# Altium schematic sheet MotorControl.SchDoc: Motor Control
size A4; SheetNumber: 17; SheetTotal: 23
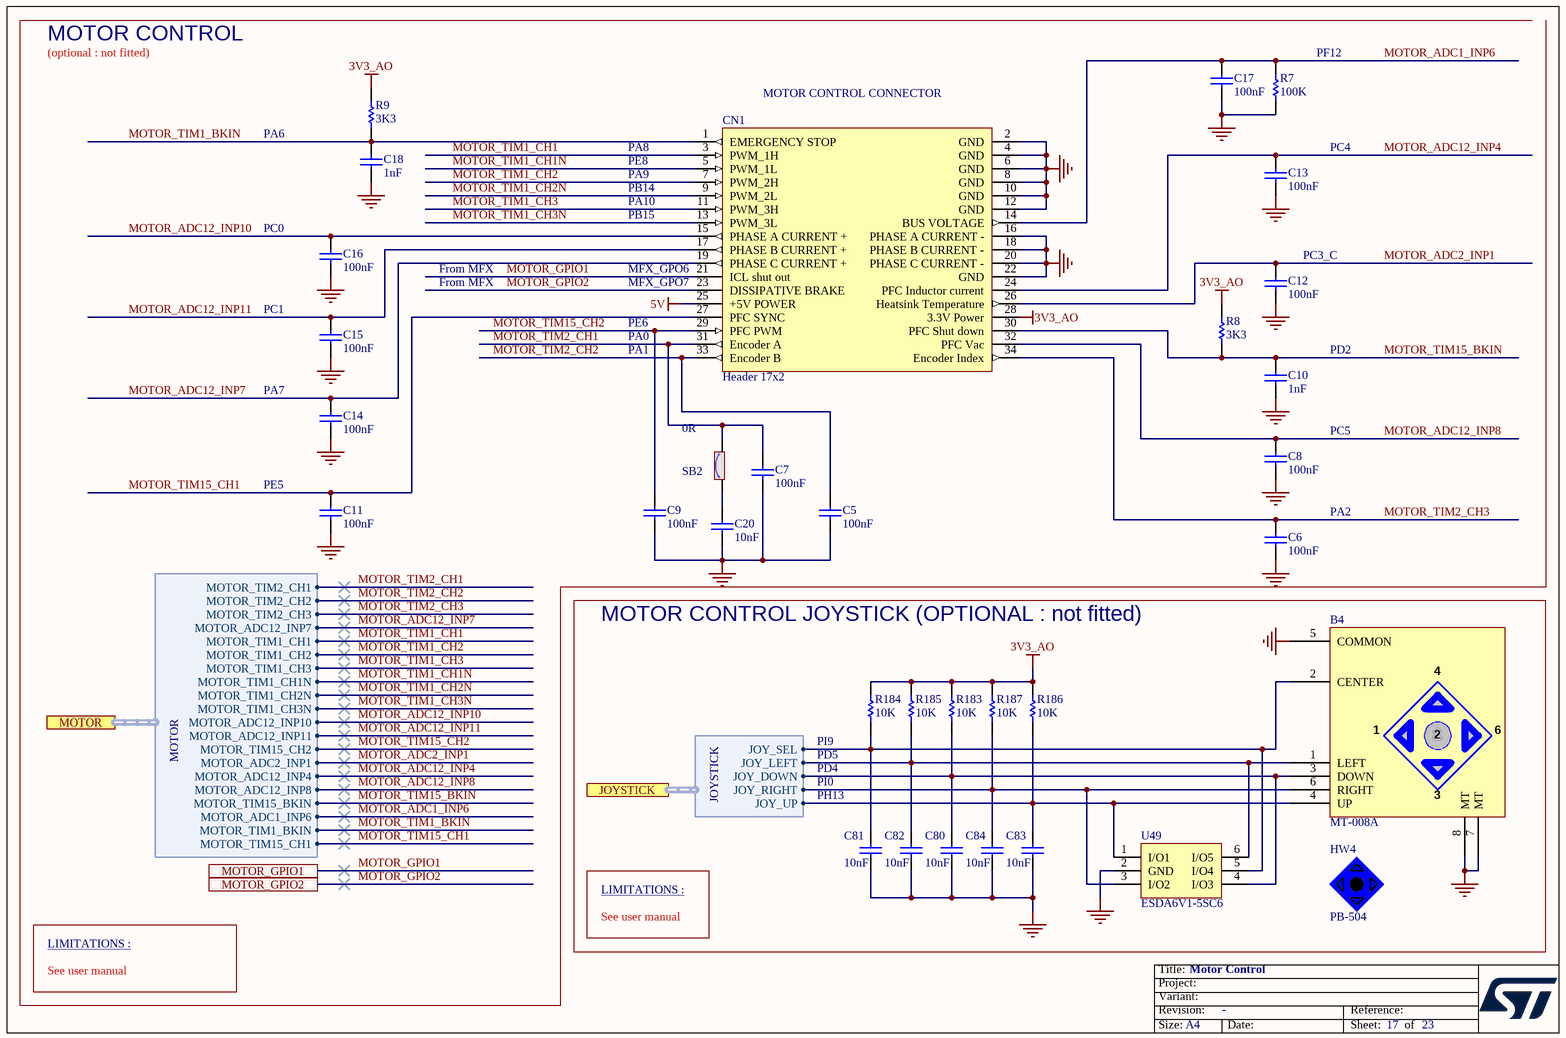
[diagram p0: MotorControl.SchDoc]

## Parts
B4  value MT-008A  [SWI_XIEJIA_MT-008A_6P]  (hidden comment: Joystick MT-008A_M)
C5  value 100nF  [C0402]  (hidden comment: Capacitor)
C6  value 100nF  [C0402]  (hidden comment: Capacitor)
C7  value 100nF  [C0402]  (hidden comment: Capacitor)
C8  value 100nF  [C0402]  (hidden comment: Capacitor)
C9  value 100nF  [C0402]  (hidden comment: Capacitor)
C10  value 1nF  [C0402]  (hidden comment: Capacitor)
C11  value 100nF  [C0402]  (hidden comment: Capacitor)
C12  value 100nF  [C0402]  (hidden comment: Capacitor)
C13  value 100nF  [C0402]  (hidden comment: Capacitor)
C14  value 100nF  [C0402]  (hidden comment: Capacitor)
C15  value 100nF  [C0402]  (hidden comment: Capacitor)
C16  value 100nF  [C0402]  (hidden comment: Capacitor)
C17  value 100nF  [C0402]  (hidden comment: Capacitor)
C18  value 1nF  [C0402]  (hidden comment: Capacitor)
C20  value 10nF  [C0402]  (hidden comment: Capacitor)
C80  value 10nF  [C0402]  (hidden comment: Capacitor)
C81  value 10nF  [C0402]  (hidden comment: Capacitor)
C82  value 10nF  [C0402]  (hidden comment: Capacitor)
C83  value 10nF  [C0402]  (hidden comment: Capacitor)
C84  value 10nF  [C0402]  (hidden comment: Capacitor)
CN1  value Header 17x2  [CON_SAMTEC_TST-117-01-T-D]  (hidden comment: Header 17x2 IDC34 MotorControl)
HW4  value PB-504  (hidden comment: JOYSTICK_BLUE_HAT)  (mechanical)
R7  value 100K  [R0603]  (hidden comment: Resistor)
R8  value 3K3  [R0402]  (hidden comment: Resistor)
R9  value 3K3  [R0402]  (hidden comment: Resistor)
R183  value 10K  [R0402]  (hidden comment: Resistor)
R184  value 10K  [R0402]  (hidden comment: Resistor)
R185  value 10K  [R0402]  (hidden comment: Resistor)
R186  value 10K  [R0402]  (hidden comment: Resistor)
R187  value 10K  [R0402]  (hidden comment: Resistor)
SB2  value 0R  [SOLDER-BRIDGE_R0603-0R]  (hidden comment: SB_ON)
U49  ESDA6V1-5SC6  [ESD_SOT23-6L]

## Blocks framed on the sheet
MOTOR CONTROL JOYSTICK (OPTIONAL : not fitted): B4 C80-C84 HW4 R183-R187 U49

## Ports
JOYSTICK (harness JOYSTICK), MOTOR (harness MOTOR), MOTOR_GPIO1, MOTOR_GPIO2

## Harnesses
MOTOR: MOTOR_TIM2_CH1, MOTOR_TIM2_CH2, MOTOR_TIM2_CH3, MOTOR_ADC12_INP7, MOTOR_TIM1_CH1, MOTOR_TIM1_CH2, MOTOR_TIM1_CH3, MOTOR_TIM1_CH1N, MOTOR_TIM1_CH2N, MOTOR_TIM1_CH3N, MOTOR_ADC12_INP10, MOTOR_ADC12_INP11, MOTOR_TIM15_CH2, MOTOR_ADC2_INP1, MOTOR_ADC12_INP4, MOTOR_ADC12_INP8, MOTOR_TIM15_BKIN, MOTOR_ADC1_INP6, MOTOR_TIM1_BKIN, MOTOR_TIM15_CH1
JOYSTICK: JOY_SEL, JOY_LEFT, JOY_DOWN, JOY_RIGHT, JOY_UP

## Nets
3V3_AO: CN1.28(3.3V_Power) R8.2 R9.2 R183.2 R184.2 R185.2 R186.2 R187.2
5V: CN1.25(+5V_POWER)
GND: B4.5(COMMON) B4.7(MT) B4.8(MT) C5.1 C6.1 C7.1 C8.1 C9.1 C10.1 C11.1 C12.1 C13.1 C14.1 C15.1 C16.1 C17.1 C18.1 C20.1 C80.1 C81.1 C82.1 C83.1 C84.1 CN1.2(GND) CN1.4(GND) CN1.6(GND) CN1.8(GND) CN1.10(GND) CN1.12(GND) CN1.16(PHASE_A_CURRENT_-) CN1.18(PHASE_B_CURRENT_-) CN1.20(PHASE_C_CURRENT_-) CN1.22(GND) R7.1 U49.2(GND)
MOTOR_ADC1_INP6: C17.2 CN1.14(BUS_VOLTAGE) R7.2 ; port MOTOR.MOTOR_ADC1_INP6
MOTOR_ADC2_INP1: C12.2 CN1.26(Heatsink_Temperature) ; port MOTOR.MOTOR_ADC2_INP1
MOTOR_ADC12_INP4: C13.2 CN1.24(PFC_Inductor_current) ; port MOTOR.MOTOR_ADC12_INP4
MOTOR_ADC12_INP7: C14.2 CN1.19(PHASE_C_CURRENT_+) ; port MOTOR.MOTOR_ADC12_INP7
MOTOR_ADC12_INP8: C8.2 CN1.32(PFC_Vac) ; port MOTOR.MOTOR_ADC12_INP8
MOTOR_ADC12_INP10: C16.2 CN1.15(PHASE_A_CURRENT_+) ; port MOTOR.MOTOR_ADC12_INP10
MOTOR_ADC12_INP11: C15.2 CN1.17(PHASE_B_CURRENT_+) ; port MOTOR.MOTOR_ADC12_INP11
MOTOR_GPIO1: CN1.21(ICL_shut_out) ; port MOTOR_GPIO1
MOTOR_GPIO2: CN1.23(DISSIPATIVE_BRAKE) ; port MOTOR_GPIO2
MOTOR_TIM1_BKIN: C18.2 CN1.1(EMERGENCY_STOP) R9.1 ; port MOTOR.MOTOR_TIM1_BKIN
MOTOR_TIM1_CH1: CN1.3(PWM_1H) ; port MOTOR.MOTOR_TIM1_CH1
MOTOR_TIM1_CH1N: CN1.5(PWM_1L) ; port MOTOR.MOTOR_TIM1_CH1N
MOTOR_TIM1_CH2: CN1.7(PWM_2H) ; port MOTOR.MOTOR_TIM1_CH2
MOTOR_TIM1_CH2N: CN1.9(PWM_2L) ; port MOTOR.MOTOR_TIM1_CH2N
MOTOR_TIM1_CH3: CN1.11(PWM_3H) ; port MOTOR.MOTOR_TIM1_CH3
MOTOR_TIM1_CH3N: CN1.13(PWM_3L) ; port MOTOR.MOTOR_TIM1_CH3N
MOTOR_TIM2_CH1: C7.2 CN1.31(Encoder_A) SB2.1 ; port MOTOR.MOTOR_TIM2_CH1
MOTOR_TIM2_CH2: C5.2 CN1.33(Encoder_B) ; port MOTOR.MOTOR_TIM2_CH2
MOTOR_TIM2_CH3: C6.2 CN1.34(Encoder_Index) ; port MOTOR.MOTOR_TIM2_CH3
MOTOR_TIM15_BKIN: C10.2 CN1.30(PFC_Shut_down) R8.1 ; port MOTOR.MOTOR_TIM15_BKIN
MOTOR_TIM15_CH1: C11.2 CN1.27(PFC_SYNC) ; port MOTOR.MOTOR_TIM15_CH1
MOTOR_TIM15_CH2: C9.2 CN1.29(PFC_PWM) ; port MOTOR.MOTOR_TIM15_CH2
NetB4_1: B4.1(LEFT) C82.2 R185.1 U49.6(I/O5) ; port JOYSTICK.JOY_LEFT
NetB4_2: B4.2(CENTER) C81.2 R184.1 U49.5(I/O4) ; port JOYSTICK.JOY_SEL
NetB4_3: B4.3(DOWN) C80.2 R183.1 U49.4(I/O3) ; port JOYSTICK.JOY_DOWN
NetB4_4: B4.4(UP) C83.2 R186.1 U49.1(I/O1) ; port JOYSTICK.JOY_UP
NetB4_6: B4.6(RIGHT) C84.2 R187.1 U49.3(I/O2) ; port JOYSTICK.JOY_RIGHT
NetC20_2: C20.2 SB2.2

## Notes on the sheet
- MOTOR CONTROL
- (optional : not fitted)
- (near CN1) MOTOR CONTROL CONNECTOR
- (near R7) PF12
- PA6
- PA9
- PA8
- PE8
- PC4
- (near C16) PC0
- PB14
- PB15
- PA10
- PC1
- From MFX
- (near CN1) MFX_GPO6
- (near CN1) MFX_GPO7
- (near C12) PC3_C
- PA1
- PA0
- PE6
- PD2
- PA7
- PC5
- PE5
- PA2
- (near R184) PD5
- PD4
- PI0
- (near R184) PI9
- PH13
- LIMITATIONS :
- See user manual

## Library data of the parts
B4 = MCD-00132: Joystick, 4 dir, 1 OK; Part_Type: Misc; Manufacturer: XIEJIA Electronics; BMS_Part_Number: 9180124; Part_Preference: Recommended; Provided_By: SUBCO; Component_Country_Of_Origin: Unknown; ID: 2736; ShowFields: YES
C5-C9 C11-C17 = MCD-00006: Capacitor, MLCC, 100nF, 16V, X7R, 10%, 0402, T=0.5mm; Manufacturer_Part_Number: CC0402KRX7R7BB104; Manufacturer: YAGEO; Alternate_Manufacturer_Part_Number: GCM155R71C104KA55D; Alternate_Manufacturer: MURATA; Part_Preference: Recommended; Partial_Alternate_Internal_Part_Number: MCD-03299; Provided_By: SUBCO; ECCN_US: EAR99; ECCN_EU: NEC; Component_Country_Of_Origin: China; ID: 2474; Order_Code_RS: 9402047; ShowFields: YES
C10 C18 = MCD-00198: Capacitor, MLCC, 1nF, 16V, X7R, 10%, 0402, T=0.5mm; Manufacturer_Part_Number: CC0402KRX7R7BB102; Manufacturer: YAGEO; Part_Preference: Recommended; Provided_By: SUBCO; ECCN_US: EAR99; ECCN_EU: NEC; Component_Country_Of_Origin: China; ID: 2665; ShowFields: YES
C20 C80-C84 = MCD-00011: Capacitor, MLCC, 10nF, 16V, X7R, 10%, 0402, T=0.5mm; Manufacturer_Part_Number: CC0402KRX7R7BB103; Manufacturer: YAGEO; Part_Preference: Recommended; Provided_By: SUBCO; ECCN_US: EAR99; ECCN_EU: NEC; Component_Country_Of_Origin: China; ID: 2469; Order_Code_RS: 3019275; ShowFields: YES
CN1 = MCD-00583: Header, 17x2, 2.54mm, VR, TH, Height 8.89mm/2.92mm, shrouded; Manufacturer_Part_Number: TST-117-01-T-D; Manufacturer: SAMTEC; Part_Type: Connector; Alternate_Manufacturer_Part_Number: BHFS03-34G01BT1; Alternate_Manufacturer: WINPIN; Part_Preference: Recommended; Provided_By: SUBCO; Component_Country_Of_Origin: China, Costa Rica, Malaysia, USA, Vietnam; ID: 3161; ShowFields: YES
HW4 = MCD-01337: Joystick Blue Hat; Part_Type: Misc; Manufacturer: JIUBABA; Part_Preference: Alternate; Provided_By: SUBCO; Alternate_EMS: A; Component_Country_Of_Origin: Unknown; ID: 3437; ShowFields: YES
R7 = MCD-00223: Resistor,100K,0603,1%,1/10W; Manufacturer_Part_Number: RC0603FR-07100KL; Manufacturer: YAGEO; Part_Preference: Recommended; Provided_By: SUBCO; ECCN_US: EAR99; ECCN_EU: NEC; Component_Country_Of_Origin: China; ID: 2647; ShowFields: YES
R8 R9 = MCD-00184: Resistor,3K3,0402,1%,1/16W; Manufacturer_Part_Number: RC0402FR-073K3L; Manufacturer: YAGEO; BMS_Part_Number: 9131946; Part_Preference: Recommended; Provided_By: SUBCO; ECCN_US: EAR99; ECCN_EU: NEC; Component_Country_Of_Origin: China; ID: 2684; ShowFields: YES
R183-R187 = MCD-00053: Resistor,10K,0402,1%,1/16W; Manufacturer_Part_Number: RC0402FR-0710KL; Manufacturer: YAGEO; BMS_Part_Number: 9131590; Part_Preference: Recommended; Provided_By: SUBCO; ECCN_US: EAR99; ECCN_EU: NEC; Component_Country_Of_Origin: China; ID: 2539; Order_Code_RS: 9239359; ShowFields: YES
SB2 = MCD-00071: Solder Bridge ON; Part_Type: Resistor; Manufacturer_Part_Number: RC0603JR-070RL; Manufacturer: YAGEO; Manufacturer_HQ_COO: Unknown; Part_Preference: Recommended; Provided_By: SUBCO; Component_Country_Of_Origin: China; ID: 2521; Order_Code_RS: 199-5647; ShowFields: YES
U49 = MCD-01066: 5 unidirectional Transil diodes ESD protection; Part_Type: Diode; Manufacturer: STMICROELECTRONICS; BMS_Part_Number: 9179044; Manufacturer_HQ_COO: EU; Part_Preference: Recommended; Provided_By: SUBCO with ST control; ECCN_US: EAR99; ECCN_EU: NEC; Component_Country_Of_Origin: China; ID: 3425; Order_Code_RS: 250-066; ShowFields: YES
